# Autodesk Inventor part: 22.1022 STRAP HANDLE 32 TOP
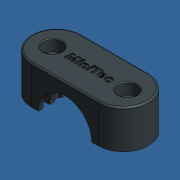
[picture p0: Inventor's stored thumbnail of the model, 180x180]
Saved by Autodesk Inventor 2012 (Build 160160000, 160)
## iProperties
Created: 2009-04
Part Number: 22.1022 STRAP HANDLE 32 TOP
Document SubType Name: Modellieren
Designer: Pleli-Schmidt
Material: ABS Plastic
Mass: 20.7421 g
Surface Area: 138.98 cm^2
Volume: 19.5681 cm^3
Density: 1.06 g/cm^3
Description: Schelle 32 Einzelteil
Material: ABS Plastik
Bezeichnung: Schelle 32 Einzelteil
Artikelnr: 221022/1
Lieferantennr: 72401
Zeichnungsnr: 22-1022-1FZ.000
MiniTec_ID: 221022/1
Teileart: K
Lieferant: MiniTec
Title: Schelle 32 Einzelteil
Author: Pleli-Schmidt
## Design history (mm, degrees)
feature "Basis1"
body "Solid1"
